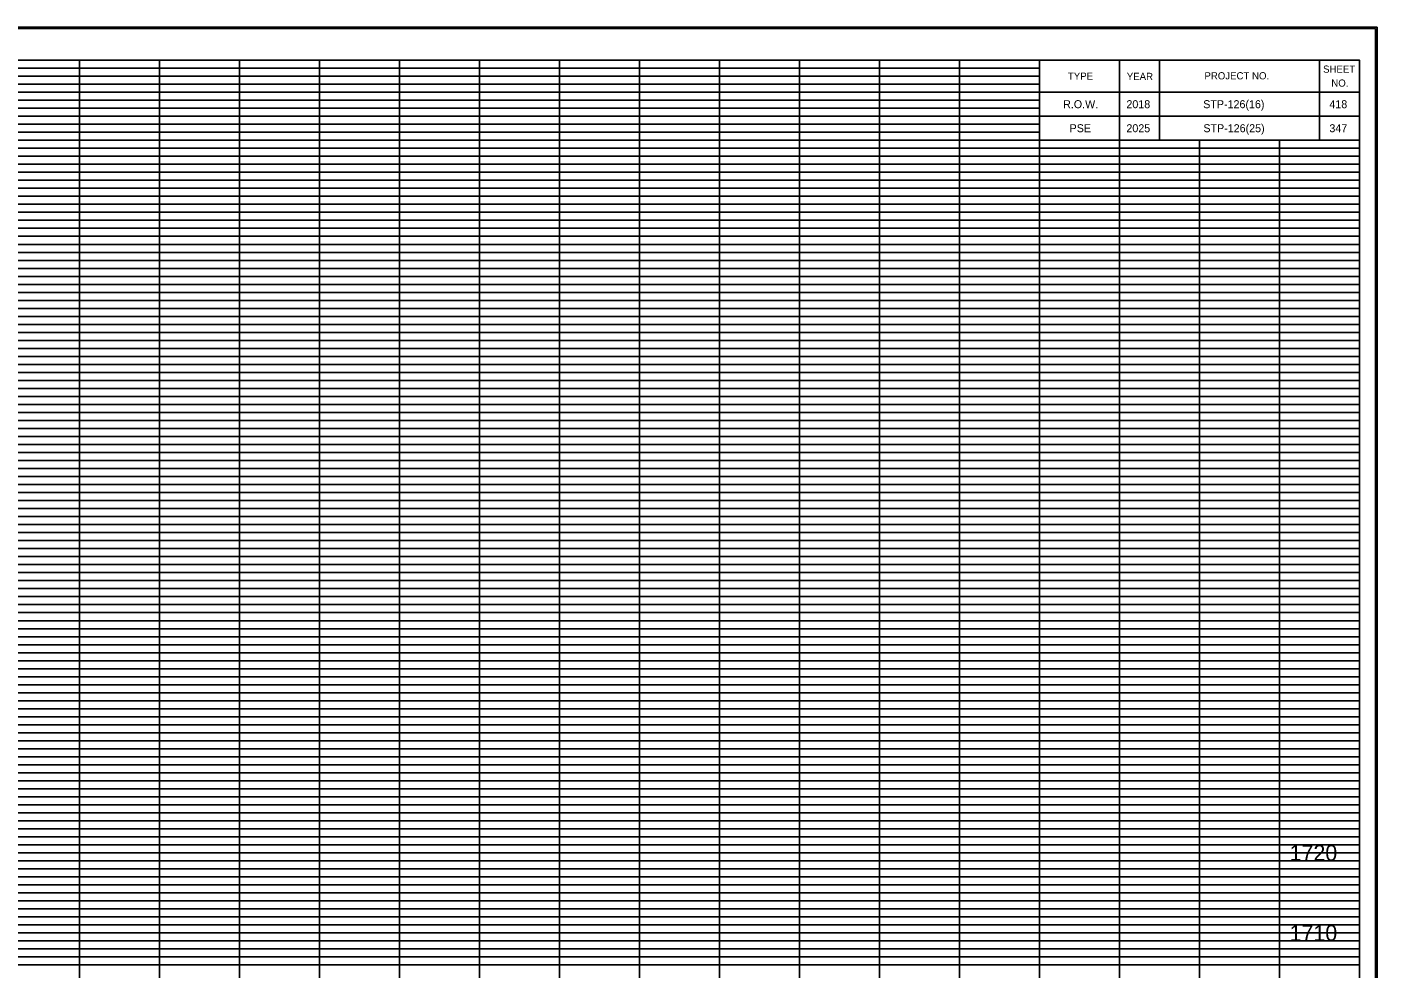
# Model space of a CAD drawing. Extents: x 980 to 2228, y 978 to 2394.
# Drawn here: x 1153.4 to 1322.2, y 1906.5 to 2024.1 of the extents above; entities that cross this region are included whole.
import ezdxf

# ---------------------------------------------------------------- set-up
doc = ezdxf.new("R2010")
doc.units = 0
for name, color, linetype in [('DESIGN - SCRATCH - User 1', 7, 'Continuous'), ('DESIGN - SHEET - Corner Text', 7, 'Continuous'), ('DESIGN - SHEET - Light Grid', 7, 'Continuous'), ('DESIGN - SHEET - Linework', 7, 'Continuous'), ('DESIGN - SHEET - Plot Shape', 7, 'Continuous'), ('DESIGN - TYPICAL - Finished Grade and Subgrade', 7, 'Continuous')]:
    doc.layers.add(name, color=color, linetype=linetype)

# ---------------------------------------------------------------- blocks, each defined once
blk = doc.blocks.new('XSTSHT')
at = {"layer": 'DESIGN - SCRATCH - User 1'}
for p, q in [((28.5, 20.45), (28.5, 20.45)), ((29.24, 20.45), (29.24, 20.45)), ((30.49, 20.45), (30.49, 20.45)), ((31.74, 20.45), (31.74, 20.45)), ((28.5, 20.15), (28.5, 20.15)), ((29.24, 20.15), (29.24, 20.15)), ((30.49, 20.15), (30.49, 20.15)), ((31.74, 20.15), (31.74, 20.15))]:
    blk.add_line(p, q, dxfattribs=at)
at = {"layer": 'DESIGN - SHEET - Light Grid'}
for p, q in [((8, 20.9), (16, 20.9)), ((8, 20.8), (16, 20.8)), ((16, 20.9), (24, 20.9)), ((16, 20.8), (24, 20.8)), ((24, 20.9), (28, 20.9)), ((24, 20.8), (28, 20.8)), ((8, 20.7), (16, 20.7)), ((8, 20.6), (16, 20.6)), ((16, 20.7), (24, 20.7)), ((16, 20.6), (24, 20.6)), ((24, 20.7), (28, 20.7)), ((24, 20.6), (28, 20.6)), ((8, 20.5), (16, 20.5)), ((16, 20.5), (24, 20.5)), ((24, 20.5), (28, 20.5)), ((8, 20.4), (16, 20.4)), ((8, 20.3), (16, 20.3)), ((16, 20.4), (24, 20.4)), ((16, 20.3), (24, 20.3)), ((24, 20.4), (28, 20.4)), ((24, 20.3), (28, 20.3)), ((8, 20.2), (16, 20.2)), ((8, 20.1), (16, 20.1)), ((16, 20.2), (24, 20.2)), ((16, 20.1), (24, 20.1)), ((24, 20.2), (28, 20.2)), ((24, 20.1), (28, 20.1)), ((8, 19.9), (16, 19.9)), ((8, 19.8), (16, 19.8)), ((16, 19.9), (24, 19.9)), ((16, 19.8), (24, 19.8)), ((24, 19.9), (32, 19.9)), ((24, 19.8), (32, 19.8)), ((8, 19.7), (16, 19.7)), ((8, 19.6), (16, 19.6)), ((16, 19.7), (24, 19.7)), ((16, 19.6), (24, 19.6)), ((24, 19.7), (32, 19.7)), ((24, 19.6), (32, 19.6)), ((8, 19.5), (16, 19.5)), ((16, 19.5), (24, 19.5)), ((24, 19.5), (32, 19.5)), ((8, 19.4), (16, 19.4)), ((8, 19.3), (16, 19.3)), ((16, 19.4), (24, 19.4)), ((16, 19.3), (24, 19.3)), ((24, 19.4), (32, 19.4)), ((24, 19.3), (32, 19.3)), ((8, 19.2), (16, 19.2)), ((8, 19.1), (16, 19.1)), ((16, 19.2), (24, 19.2)), ((16, 19.1), (24, 19.1)), ((24, 19.2), (32, 19.2)), ((24, 19.1), (32, 19.1)), ((8, 18.9), (16, 18.9)), ((16, 18.9), (24, 18.9)), ((24, 18.9), (32, 18.9)), ((8, 18.8), (16, 18.8)), ((16, 18.8), (24, 18.8)), ((24, 18.8), (32, 18.8)), ((8, 18.7), (16, 18.7)), ((8, 18.6), (16, 18.6)), ((16, 18.7), (24, 18.7)), ((16, 18.6), (24, 18.6)), ((24, 18.7), (32, 18.7)), ((24, 18.6), (32, 18.6)), ((8, 18.5), (16, 18.5)), ((8, 18.4), (16, 18.4)), ((16, 18.5), (24, 18.5)), ((16, 18.4), (24, 18.4)), ((24, 18.5), (32, 18.5)), ((24, 18.4), (32, 18.4)), ((8, 18.3), (16, 18.3)), ((16, 18.3), (24, 18.3)), ((24, 18.3), (32, 18.3)), ((8, 18.2), (16, 18.2)), ((8, 18.1), (16, 18.1)), ((16, 18.2), (24, 18.2)), ((16, 18.1), (24, 18.1)), ((24, 18.2), (32, 18.2)), ((24, 18.1), (32, 18.1)), ((8, 17.9), (16, 17.9)), ((16, 17.9), (24, 17.9)), ((24, 17.9), (32, 17.9)), ((8, 17.8), (16, 17.8)), ((16, 17.8), (24, 17.8)), ((24, 17.8), (32, 17.8)), ((8, 17.7), (16, 17.7)), ((8, 17.6), (16, 17.6)), ((16, 17.7), (24, 17.7)), ((16, 17.6), (24, 17.6)), ((24, 17.7), (32, 17.7)), ((24, 17.6), (32, 17.6)), ((8, 17.5), (16, 17.5)), ((8, 17.4), (16, 17.4)), ((16, 17.5), (24, 17.5)), ((16, 17.4), (24, 17.4)), ((24, 17.5), (32, 17.5)), ((24, 17.4), (32, 17.4)), ((8, 17.3), (16, 17.3)), ((16, 17.3), (24, 17.3)), ((24, 17.3), (32, 17.3)), ((8, 17.2), (16, 17.2)), ((8, 17.1), (16, 17.1)), ((16, 17.2), (24, 17.2)), ((16, 17.1), (24, 17.1)), ((24, 17.2), (32, 17.2)), ((24, 17.1), (32, 17.1)), ((8, 16.9), (16, 16.9)), ((16, 16.9), (24, 16.9)), ((24, 16.9), (32, 16.9)), ((8, 16.8), (16, 16.8)), ((16, 16.8), (24, 16.8)), ((24, 16.8), (32, 16.8)), ((8, 16.7), (16, 16.7)), ((8, 16.6), (16, 16.6)), ((16, 16.7), (24, 16.7)), ((16, 16.6), (24, 16.6)), ((24, 16.7), (32, 16.7)), ((24, 16.6), (32, 16.6)), ((8, 16.5), (16, 16.5)), ((8, 16.4), (16, 16.4)), ((16, 16.5), (24, 16.5)), ((16, 16.4), (24, 16.4)), ((24, 16.5), (32, 16.5)), ((24, 16.4), (32, 16.4)), ((8, 16.3), (16, 16.3)), ((8, 16.2), (16, 16.2)), ((16, 16.3), (24, 16.3)), ((16, 16.2), (24, 16.2)), ((24, 16.3), (32, 16.3)), ((24, 16.2), (32, 16.2)), ((8, 16.1), (16, 16.1)), ((16, 16.1), (24, 16.1)), ((24, 16.1), (32, 16.1)), ((8, 15.9), (16, 15.9)), ((16, 15.9), (24, 15.9)), ((24, 15.9), (32, 15.9)), ((8, 15.8), (16, 15.8)), ((8, 15.7), (16, 15.7)), ((16, 15.8), (24, 15.8)), ((16, 15.7), (24, 15.7)), ((24, 15.8), (32, 15.8)), ((24, 15.7), (32, 15.7)), ((8, 15.6), (16, 15.6)), ((16, 15.6), (24, 15.6)), ((24, 15.6), (32, 15.6)), ((8, 15.5), (16, 15.5)), ((8, 15.4), (16, 15.4)), ((16, 15.5), (24, 15.5)), ((16, 15.4), (24, 15.4)), ((24, 15.5), (32, 15.5)), ((24, 15.4), (32, 15.4)), ((8, 15.3), (16, 15.3)), ((8, 15.2), (16, 15.2)), ((16, 15.3), (24, 15.3)), ((16, 15.2), (24, 15.2)), ((24, 15.3), (32, 15.3)), ((24, 15.2), (32, 15.2)), ((8, 15.1), (16, 15.1)), ((16, 15.1), (24, 15.1)), ((24, 15.1), (32, 15.1)), ((8, 14.9), (16, 14.9)), ((16, 14.9), (24, 14.9)), ((24, 14.9), (32, 14.9)), ((8, 14.8), (16, 14.8)), ((8, 14.7), (16, 14.7)), ((16, 14.8), (24, 14.8)), ((16, 14.7), (24, 14.7)), ((24, 14.8), (32, 14.8)), ((24, 14.7), (32, 14.7)), ((8, 14.6), (16, 14.6)), ((16, 14.6), (24, 14.6)), ((24, 14.6), (32, 14.6)), ((8, 14.5), (16, 14.5)), ((8, 14.4), (16, 14.4)), ((16, 14.5), (24, 14.5)), ((16, 14.4), (24, 14.4)), ((24, 14.5), (32, 14.5)), ((24, 14.4), (32, 14.4)), ((8, 14.3), (16, 14.3)), ((8, 14.2), (16, 14.2)), ((16, 14.3), (24, 14.3)), ((16, 14.2), (24, 14.2)), ((24, 14.3), (32, 14.3)), ((24, 14.2), (32, 14.2)), ((8, 14.1), (16, 14.1)), ((16, 14.1), (24, 14.1)), ((24, 14.1), (32, 14.1)), ((8, 13.9), (16, 13.9)), ((16, 13.9), (24, 13.9)), ((24, 13.9), (32, 13.9)), ((8, 13.8), (16, 13.8)), ((8, 13.7), (16, 13.7)), ((16, 13.8), (24, 13.8)), ((16, 13.7), (24, 13.7)), ((24, 13.8), (32, 13.8)), ((24, 13.7), (32, 13.7)), ((8, 13.6), (16, 13.6)), ((8, 13.5), (16, 13.5)), ((16, 13.6), (24, 13.6)), ((16, 13.5), (24, 13.5)), ((24, 13.6), (32, 13.6)), ((24, 13.5), (32, 13.5)), ((8, 13.4), (16, 13.4)), ((16, 13.4), (24, 13.4)), ((24, 13.4), (32, 13.4)), ((8, 13.3), (16, 13.3)), ((8, 13.2), (16, 13.2)), ((16, 13.3), (24, 13.3)), ((16, 13.2), (24, 13.2)), ((24, 13.3), (32, 13.3)), ((24, 13.2), (32, 13.2)), ((8, 13.1), (16, 13.1)), ((16, 13.1), (24, 13.1)), ((24, 13.1), (32, 13.1)), ((8, 12.9), (16, 12.9)), ((16, 12.9), (24, 12.9)), ((24, 12.9), (32, 12.9)), ((8, 12.8), (16, 12.8)), ((8, 12.7), (16, 12.7)), ((16, 12.8), (24, 12.8)), ((16, 12.7), (24, 12.7)), ((24, 12.8), (32, 12.8)), ((24, 12.7), (32, 12.7)), ((8, 12.6), (16, 12.6)), ((8, 12.5), (16, 12.5)), ((16, 12.6), (24, 12.6)), ((16, 12.5), (24, 12.5)), ((24, 12.6), (32, 12.6)), ((24, 12.5), (32, 12.5)), ((8, 12.4), (16, 12.4)), ((16, 12.4), (24, 12.4)), ((24, 12.4), (32, 12.4)), ((8, 12.3), (16, 12.3)), ((8, 12.2), (16, 12.2)), ((16, 12.3), (24, 12.3)), ((16, 12.2), (24, 12.2)), ((24, 12.3), (32, 12.3)), ((24, 12.2), (32, 12.2)), ((8, 12.1), (16, 12.1)), ((16, 12.1), (24, 12.1)), ((24, 12.1), (32, 12.1)), ((8, 11.9), (16, 11.9)), ((16, 11.9), (24, 11.9)), ((24, 11.9), (32, 11.9)), ((8, 11.8), (16, 11.8)), ((8, 11.7), (16, 11.7)), ((16, 11.8), (24, 11.8)), ((16, 11.7), (24, 11.7)), ((24, 11.8), (32, 11.8)), ((24, 11.7), (32, 11.7)), ((8, 11.6), (16, 11.6)), ((8, 11.5), (16, 11.5)), ((16, 11.6), (24, 11.6)), ((16, 11.5), (24, 11.5)), ((24, 11.6), (32, 11.6)), ((24, 11.5), (32, 11.5)), ((8, 11.4), (16, 11.4)), ((16, 11.4), (24, 11.4)), ((24, 11.4), (32, 11.4)), ((8, 11.3), (16, 11.3)), ((8, 11.2), (16, 11.2)), ((16, 11.3), (24, 11.3)), ((16, 11.2), (24, 11.2)), ((24, 11.3), (32, 11.3)), ((24, 11.2), (32, 11.2)), ((8, 11.1), (16, 11.1)), ((16, 11.1), (24, 11.1)), ((24, 11.1), (32, 11.1)), ((8, 10.9), (16, 10.9)), ((8, 10.8), (16, 10.8)), ((16, 10.9), (24, 10.9)), ((16, 10.8), (24, 10.8)), ((24, 10.9), (32, 10.9)), ((24, 10.8), (32, 10.8)), ((8, 10.7), (16, 10.7)), ((16, 10.7), (24, 10.7)), ((24, 10.7), (32, 10.7)), ((8, 10.6), (16, 10.6)), ((8, 10.5), (16, 10.5)), ((16, 10.6), (24, 10.6)), ((16, 10.5), (24, 10.5)), ((24, 10.6), (32, 10.6)), ((24, 10.5), (32, 10.5)), ((8, 10.4), (16, 10.4)), ((8, 10.3), (16, 10.3)), ((16, 10.4), (24, 10.4)), ((16, 10.3), (24, 10.3)), ((24, 10.4), (32, 10.4)), ((24, 10.3), (32, 10.3)), ((8, 10.2), (16, 10.2)), ((16, 10.2), (24, 10.2)), ((24, 10.2), (32, 10.2)), ((8, 10.1), (16, 10.1)), ((16, 10.1), (24, 10.1)), ((24, 10.1), (32, 10.1)), ((8, 9.9), (16, 9.9)), ((8, 9.8), (16, 9.8)), ((16, 9.9), (24, 9.9)), ((16, 9.8), (24, 9.8)), ((24, 9.9), (32, 9.9)), ((24, 9.8), (32, 9.8)), ((8, 9.7), (16, 9.7)), ((16, 9.7), (24, 9.7)), ((24, 9.7), (32, 9.7))]:
    blk.add_line(p, q, dxfattribs=at)
at = {"layer": 'DESIGN - SHEET - Linework'}
for p, q in [((-1.823, 21.414), (32.217, 21.414)), ((32.217, 21.414), (32.217, -0.414)), ((16, 0), (16, 21)), ((17, 0), (17, 21)), ((18, 0), (18, 21)), ((19, 0), (19, 21)), ((20, 0), (20, 21)), ((21, 0), (21, 21)), ((22, 0), (22, 21)), ((23, 0), (23, 21)), ((24, 0), (24, 21)), ((25, 0), (25, 21)), ((26, 0), (26, 21)), ((27, 0), (27, 21)), ((0, 20), (28, 20)), ((28, 0), (28, 20)), ((29, 0), (29, 20)), ((30, 0), (30, 20)), ((31, 0), (31, 20)), ((0, 19), (32, 19)), ((0, 18), (32, 18)), ((0, 17), (32, 17)), ((0, 16), (32, 16)), ((0, 15), (32, 15)), ((0, 14), (32, 14)), ((0, 13), (32, 13)), ((0, 12), (32, 12)), ((0, 11), (32, 11)), ((0, 10), (32, 10))]:
    blk.add_line(p, q, dxfattribs=at)
for points in [[(0, 21), (0, 0), (32, 0), (32, 21), (0, 21)], [(28, 21), (28, 20), (32, 20), (32, 21), (31.5, 21), (31.5, 20), (29.5, 20), (29.5, 21), (29, 21), (29, 20), (32, 20), (28, 20), (28, 20.3), (32, 20.3), (32, 20.6), (28, 20.6)]]:
    blk.add_lwpolyline(points, dxfattribs=at)
at = {"layer": 'DESIGN - SHEET - Plot Shape'}
for points in [[(-1.803, 21.394), (32.197, 21.394), (32.197, -0.394), (-1.803, -0.394)], [(-0.85, 21), (32, 21), (32, -0.25), (-0.85, -0.25)]]:
    blk.add_lwpolyline(points, close=True, dxfattribs=at)
at = {"layer": 'DESIGN - SHEET - Corner Text'}
for s, p in [('SHEET', (31.543, 20.843)), ('TYPE', (28.354, 20.756)), ('YEAR', (29.09, 20.752)), ('PROJECT NO.', (30.06, 20.76)), ('NO.', (31.646, 20.669))]:
    blk.add_text(s, height=0.09, dxfattribs=at).set_placement(p)

msp = doc.modelspace()

# ---------------------------------------------------------------- linework, layer by layer
at = {"layer": 'DESIGN - SHEET - Plot Shape'}
msp.add_lwpolyline([(991.5, 2020), (1320, 2020), (1320, 1807.5), (991.5, 1807.5)], close=True, dxfattribs=at)

# ---------------------------------------------------------------- block references
at = {"layer": 'DESIGN - TYPICAL - Finished Grade and Subgrade', "xscale": 10, "yscale": 10}
msp.add_blockref('XSTSHT', (1000, 1810), dxfattribs=at)

# ---------------------------------------------------------------- texts
at = {"layer": 'DESIGN - SHEET - Corner Text'}
for s, height, p in [('R.O.W.', 1, (1282.94, 2014)), ('2018', 1, (1290.85, 2014)), ('STP-126(16)', 1, (1300.45, 2014)), ('418', 1, (1316.22, 2014)), ('PSE', 1, (1283.75, 2011)), ('2025', 1, (1290.85, 2011)), ('STP-126(25)', 1, (1300.47, 2011)), ('347', 1, (1316.22, 2011)), ('1720', 2, (1311.25, 1920)), ('1710', 2, (1311.25, 1910))]:
    msp.add_text(s, height=height, dxfattribs=at).set_placement(p)

doc.saveas('drawing.dxf')
